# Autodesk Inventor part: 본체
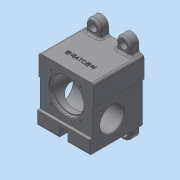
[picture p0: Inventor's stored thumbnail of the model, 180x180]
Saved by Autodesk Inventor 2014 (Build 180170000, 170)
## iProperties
Created: 2024-11
Part Number: 본체
Material: 일반
Document SubType Name: Modeling
Designer: dg
Density: 1 g/cm^3
Appearance: 기본값
Author: dg
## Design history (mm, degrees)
sketch "스케치1"
  geometry: L1 (-38, 0)-(38, 0); L2 (38, 0)-(38, -29); L3 (38, -29)-(36, -29); L4 (36, -29)-(36, -85); L5 (36, -85)-(6, -85); L6 (6, -85)-(6, -70); L7 (6, -70)-(-6, -70); L8 (-6, -70)-(-6, -85); L9 (-6, -85)-(-36, -85); L10 (-36, -85)-(-36, -29); L11 (-36, -29)-(-38, -29); L12 (-38, -29)-(-38, 0); 2 further points
  constraints: 24 end point, 10 parallel, 4 equal length, 1 coincident, 1 horizontal, 1 midpoint, 1 perpendicular
  dimensions: "d0" = 76 distance of L1.start L1.end; "d1" = 85 distance between parallel lines of L9 L1; "d2" = 56 distance of L9.end L10.end; "d3" = 15 distance of L7.end L8.end; "d4" = 12 distance of L6.end L7.end; "d5" = 2 distance of L10.end L11.end
extrude "돌출1" new body sketch "스케치1" distance "d6" = 74; taper "d7" = 0 deg
sketch "스케치2"
  geometry: L1 (0, 0)-(66, 0); L2 (66, 0)-(66, 4); L3 (66, 4)-(0, 4); L4 (0, 4)-(0, 0)
  constraints: 8 end point, 2 parallel, 1 horizontal, 1 perpendicular
  dimensions: "d8" = 4 distance of L1.end L2.end; "d9" = 66 distance of L2.end L3.end
extrude "돌출2" cut sketch "스케치2" stored distance "d10" = 74; taper "d11" = 0 deg
sketch "스케치3"
  geometry: L1 (-38, 0)-(38, 0) reference; L2 (36, 85)-(6, 85) reference; L3 (-6, 85)-(-36, 85) reference; L4 (-31, 85)-(-11, 85); L5 (-11, 85)-(-11, 105); L6 (-11, 105)-(-31, 105); L7 (-31, 105)-(-31, 85); L8 (11, 85)-(31, 85); L9 (31, 85)-(31, 105); L10 (31, 105)-(11, 105); L11 (11, 105)-(11, 85); L12 (-31, -20)-(-11, -20); L13 (-11, -20)-(-11, 0); L14 (-11, 0)-(-31, 0); L15 (-31, 0)-(-31, -20); L16 (11, -20)-(31, -20); L17 (31, -20)-(31, 0); L18 (31, 0)-(11, 0); L19 (11, 0)-(11, -20); 5 further points
  constraints: 32 end point, 8 parallel, 6 equal length, 6 midpoint, 4 horizontal, 4 perpendicular, 2 collinear, 2 point on line
  dimensions: "d12" = 20 distance of L5.end L6.end; "d13" = 20 distance of L6.end L4.start; "d14" = 62 distance between parallel lines of L9 L7; "d15" = 31 distance from line of point (0, 0) L7
extrude "돌출3" join sketch "스케치3" distance "d16" = 12; taper "d17" = 0 deg
fillet "모깎기1" dims "d18" = 10
sketch "스케치4" dims "d0" = 76, "d1" = 85, "d2" = 56, "d3" = 15, "d4" = 12, "d5" = 2
  geometry: L1 (0, 0)-(76, 0) reference; 2 further points
  constraints: 1 vertical alignment, 1 other
  dimensions: "d19" = 20 distance from line of point (38, 20) L1
feature "엠보싱1" sketch "스케치4" dims "d0" = 76, "d1" = 85, "d2" = 56, "d3" = 15, "d4" = 12, "d5" = 2, "d20" = 0.5, "d21" = 0
sketch "스케치5"
  geometry: L1 (4, -33)-(70, -33); L2 (4, -66)-(4, -29) reference; L3 (4, 0)-(74, 0) reference; L4 (4, -33)-(4, -9.5); L5 (4, -9.5)-(8, -9.5); L6 (8, -9.5)-(8, -11); L7 (8, -11)-(56, -11); L8 (56, -11)-(56, -15.5); L9 (56, -15.5)-(67, -15.5); L10 (67, -15.5)-(67, -18); L11 (67, -18)-(70, -18); L12 (70, -18)-(70, -33); L13 (0, -85)-(0, -70) reference; 1 further point
  constraints: 20 end point, 6 parallel, 3 perpendicular, 1 horizontal, 1 point on line
  dimensions: "d23" = 33 distance between parallel lines of L1 L3; "d24" = 66 distance of L1.start L1.end; "d25" = 47 diameter of L5 L1; "d26" = 44 diameter of L7 L1; "d27" = 35 diameter of L9 L1; "d28" = 30 diameter of L11 L1; "d29" = 4 distance of L4.end L5.end; "d30" = 56 distance between parallel lines of L13 L8; "d31" = 11 distance of L8.end L9.end
revolve "회전1" sketch "스케치5" stored, may be unused: angle "d32" = 90 deg
sketch "스케치6"
  geometry: L1 (-56, 74)-(0, 74) reference; L2 (-85, 4)-(-85, 74) reference; C1 r 16.5 at (-28, 32); 1 further point
  constraints: 1 centre point
  dimensions: "d33" = 57 distance from line of L2 C1.centre; "d34" = 42 distance from line of C1.centre L1; "d35" = 33 diameter of C1
extrude "돌출4" cut sketch "스케치6" stored distance "d36" = 12; taper "d37" = 0 deg
sketch "스케치7"
  geometry: C1 r 16.5 at (-28, 32) reference; 5 further points
  constraints: 2 horizontal alignment, 2 vertical alignment
  dimensions: "d38" = 32 distance of point (-12, 48) point (-44, 48); "d39" = 32 distance of point (-12, 16) point (-12, 48); "d40" = 16 horizontal distance of point (-12, 48) C1.centre; "d41" = 16 horizontal distance of C1.centre point (-12, 48)
hole "구멍1" sketch "스케치7" at (-44, 48), (-12, 48), (-44, 16), (-12, 16) diameter "d42" = 3.242; stored, may be unused: countersink angle "d46" = 90 deg, drill point angle "d48" = 118 deg; dims "d43" = 8, "d44" = 4, "d45" = 2, "d47" = 10
sketch "스케치8"
  geometry: C1 r 23.5 at (-38, -4) reference; A1 r 28.5 centre (-38, -4) between (-58.153, 16.153) and (-58.153, -24.153); 3 further points
  constraints: 4 point on circle, 2 horizontal alignment, 2 vertical alignment, 1 centre point, 1 coincident
  dimensions: "d49" = 57 diameter of A1; "d50" = 90 deg dimension on C1.centre point (-17.847, -24.153) point (-17.847, 16.153)
hole "구멍2" sketch "스케치8" at (-58.153, 16.153), (-58.153, -24.153), (-17.847, -24.153), (-17.847, 16.153) diameter "d51" = 3.242; stored, may be unused: countersink angle "d55" = 90 deg, drill point angle "d57" = 118 deg; dims "d52" = 8, "d53" = 4, "d54" = 2, "d56" = 10
hole "구멍3" diameter "d60" = 6.6; stored, may be unused: countersink angle "d64" = 90 deg, drill point angle "d66" = 0 deg; dims "d58" = 10, "d59" = 10, "d61" = 8, "d62" = 11, "d63" = 6.6, "d65" = 10
hole "구멍4" diameter "d69" = 6.6; stored, may be unused: countersink angle "d73" = 90 deg, drill point angle "d75" = 0 deg; dims "d67" = 10, "d68" = 10, "d70" = 8, "d71" = 11, "d72" = 6.6, "d74" = 10
hole "구멍5" diameter "d78" = 6.6; stored, may be unused: countersink angle "d82" = 90 deg, drill point angle "d84" = 0 deg; dims "d76" = 10, "d77" = 10, "d79" = 8, "d80" = 11, "d81" = 6.6, "d83" = 10
hole "구멍6" diameter "d87" = 6.6; stored, may be unused: countersink angle "d91" = 90 deg, drill point angle "d93" = 0 deg; dims "d85" = 10, "d86" = 10, "d88" = 8, "d89" = 11, "d90" = 6.6, "d92" = 10
sketch "스케치9"
  geometry: L1 (12, 0)-(0, 0) reference; 4 further points
  constraints: 2 vertical alignment, 1 midpoint
  dimensions: "d94" = 12 distance from line of point (6, 12) L1; "d95" = 40 distance of point (6, 52) point (6, 12)
hole "구멍7" sketch "스케치9" at (6, 12), (6, 52) diameter "d96" = 3.242; stored, may be unused: countersink angle "d100" = 90 deg, drill point angle "d102" = 118 deg; dims "d97" = 8, "d98" = 11, "d99" = 6.6, "d101" = 10
chamfer "모따기1" distance "d103" = 1; stored, may be unused: second distance "d104" = 2, angle "d105" = 45 deg
fillet "모깎기2" dims "d106" = 3
chamfer "모따기2" distance "d107" = 1; stored, may be unused: second distance "d108" = 2, angle "d109" = 45 deg
fillet "모깎기3" dims "d110" = 0.6
fillet "모깎기4" dims "d111" = 3
fillet "모깎기5" dims "d112" = 3
chamfer "모따기3" distance "d114" = 1; stored, may be unused: second distance "d115" = 2, angle "d116" = 45 deg
fillet "모깎기7" dims "d117" = 3
fillet "모깎기8" dims "d118" = 3
fillet "모깎기9" dims "d122" = 3
chamfer "모따기5" distance "d123" = 1; stored, may be unused: second distance "d124" = 2, angle "d125" = 45 deg
fillet "모깎기10" dims "d126" = 3
node "솔리드1"
mirror "대칭1"
